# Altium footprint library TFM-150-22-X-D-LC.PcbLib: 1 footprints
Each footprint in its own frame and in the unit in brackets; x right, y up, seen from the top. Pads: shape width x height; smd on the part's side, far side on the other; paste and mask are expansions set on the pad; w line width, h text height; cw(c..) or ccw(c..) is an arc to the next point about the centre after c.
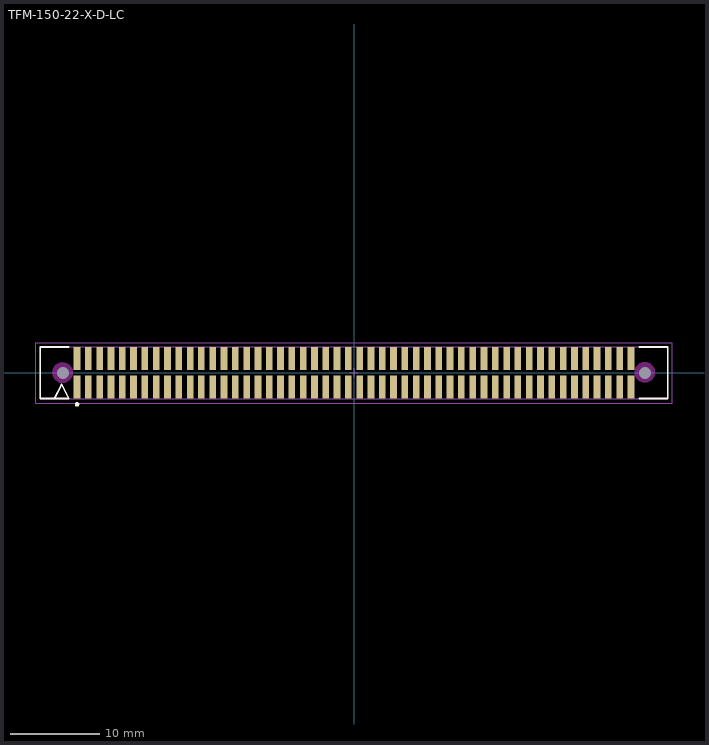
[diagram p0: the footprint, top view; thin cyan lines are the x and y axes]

## TFM-150-22-X-D-LC [mm] "1.27mm pitch, 100 pin, micro terminal strip; double row, w/locking clips, SMT"
height 5.72
pads (102):
  rect 0.75x2.6 smd mask+0: 1(-31.115,-1.6) 2(-31.115,1.6) 3(-29.845,-1.6) 4(-29.845,1.6) 5(-28.575,-1.6) 6(-28.575,1.6) 7(-27.305,-1.6) 8(-27.305,1.6) 9(-26.035,-1.6) 10(-26.035,1.6) 11(-24.765,-1.6) 12(-24.765,1.6) 13(-23.495,-1.6) 14(-23.495,1.6) 15(-22.225,-1.6) 16(-22.225,1.6) 17(-20.955,-1.6) 18(-20.955,1.6) 19(-19.685,-1.6) 20(-19.685,1.6) 21(-18.415,-1.6) 22(-18.415,1.6) 23(-17.145,-1.6) 24(-17.145,1.6) 25(-15.875,-1.6) 26(-15.875,1.6) 27(-14.605,-1.6) 28(-14.605,1.6) 29(-13.335,-1.6) 30(-13.335,1.6) 31(-12.065,-1.6) 32(-12.065,1.6) 33(-10.795,-1.6) 34(-10.795,1.6) 35(-9.525,-1.6) 36(-9.525,1.6) 37(-8.255,-1.6) 38(-8.255,1.6) 39(-6.985,-1.6) 40(-6.985,1.6) 41(-5.715,-1.6) 42(-5.715,1.6) 43(-4.445,-1.6) 44(-4.445,1.6) 45(-3.175,-1.6) 46(-3.175,1.6) 47(-1.905,-1.6) 48(-1.905,1.6) 49(-0.635,-1.6) 50(-0.635,1.6) 51(0.635,-1.6) 52(0.635,1.6) 53(1.905,-1.6) 54(1.905,1.6) 55(3.175,-1.6) 56(3.175,1.6) 57(4.445,-1.6) 58(4.445,1.6) 59(5.715,-1.6) 60(5.715,1.6) 61(6.985,-1.6) 62(6.985,1.6) 63(8.255,-1.6) 64(8.255,1.6) 65(9.525,-1.6) 66(9.525,1.6) 67(10.795,-1.6) 68(10.795,1.6) 69(12.065,-1.6) 70(12.065,1.6) 71(13.335,-1.6) 72(13.335,1.6) 73(14.605,-1.6) 74(14.605,1.6) 75(15.875,-1.6) 76(15.875,1.6) 77(17.145,-1.6) 78(17.145,1.6) 79(18.415,-1.6) 80(18.415,1.6) 81(19.685,-1.6) 82(19.685,1.6) 83(20.955,-1.6) 84(20.955,1.6) 85(22.225,-1.6) 86(22.225,1.6) 87(23.495,-1.6) 88(23.495,1.6) 89(24.765,-1.6) 90(24.765,1.6) 91(26.035,-1.6) 92(26.035,1.6) 93(27.305,-1.6) 94(27.305,1.6) 95(28.575,-1.6) 96(28.575,1.6) 97(29.845,-1.6) 98(29.845,1.6) 99(31.115,-1.6) 100(31.115,1.6)
  round 1 hole 1.35 unplated mask+0: 101(-32.703,0) 102(32.703,0)
Top Overlay:
  circle w0.25: c-31.115,-3.55 r0.125
  lines w0.2: -33.65,-2.9 -32.85,-1.3 -32.05,-2.9 ; -32.058,-2.9 -35.24,-2.9 -35.24,2.9 -32.058,2.9 ; 32.058,-2.9 35.24,-2.9 35.24,2.9 32.058,2.9
Keep-Out Layer:
  pour cut-out: 33.816,0.051 33.777,0.348 33.662,0.624 33.48,0.862 33.242,1.044 32.966,1.159 32.669,1.198 32.372,1.159 32.095,1.044 31.857,0.862 31.675,0.624 31.56,0.348 31.521,0.051 31.56,-0.246 31.675,-0.523 31.857,-0.76 32.095,-0.943 32.372,-1.057 32.669,-1.096 32.966,-1.057 33.242,-0.943 33.48,-0.76 33.662,-0.523 33.777,-0.246
  pour cut-out: -31.586,0.025 -31.626,0.325 -31.742,0.605 -31.926,0.845 -32.166,1.029 -32.445,1.144 -32.745,1.184 -33.045,1.144 -33.324,1.029 -33.564,0.845 -33.748,0.605 -33.864,0.325 -33.903,0.025 -33.864,-0.274 -33.748,-0.554 -33.564,-0.794 -33.324,-0.978 -33.045,-1.094 -32.745,-1.133 -32.445,-1.094 -32.166,-0.978 -31.926,-0.794 -31.742,-0.554 -31.626,-0.274
Mechanical 12:
  lines w0.001: -35.24,-2.9 -35.24,2.9 35.24,2.9 35.24,-2.9 -35.24,-2.9
Mechanical 13:
  lines w0.1: -33.65,-2.9 -32.85,-1.3 -32.05,-2.9 ; -35.24,-2.9 -35.24,2.9 35.24,2.9 35.24,-2.9 -35.24,-2.9
  text ".Designator" at 0,-0.127 h1.52
Mechanical 15:
  lines w0.05: -35.75,-3.4 -35.75,3.4 35.75,3.4 35.75,-3.4 -35.75,-3.4
  lines w0.1: -0.5,0 0.5,0 ; 0,-0.5 0,0.5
